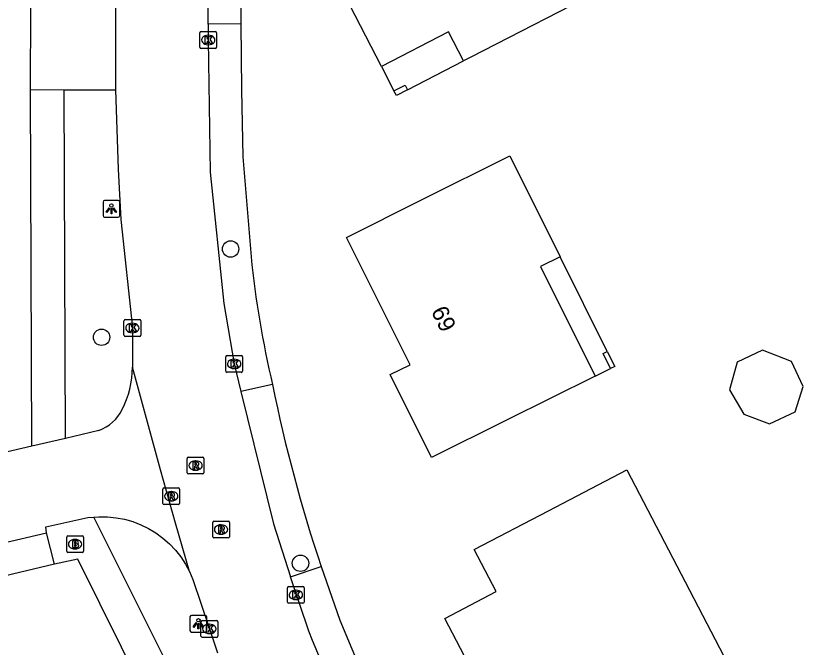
# Model space of a CAD drawing. Extents: x 162722 to 165099, y 384721 to 386283.
# Drawn here: x 163645.06 to 163692.03, y 385039.4 to 385077.05 of the extents above; entities that cross this region are included whole.
import ezdxf

# ---------------------------------------------------------------- set-up
doc = ezdxf.new("R2010")
doc.units = 0
for name, color, linetype in [('IMGEO_Boom', 7, 'Continuous'), ('IMGEO_Brandkraan', 7, 'Continuous'), ('IMGEO_Kolk', 7, 'Continuous'), ('IMGEO_Lichtpunt', 7, 'Continuous'), ('IMGEO_Pand', 7, 'Continuous'), ('IMGEO_Pand_nummerreeks', 7, 'Continuous'), ('IMGEO_Pand_overbouw', 7, 'Continuous'), ('IMGEO_Parkeervlak_open', 7, 'Continuous'), ('IMGEO_Rijbaan_lokaal_open', 7, 'Continuous'), ('IMGEO_Rioolput', 7, 'Continuous'), ('IMGEO_Voetpad_open', 7, 'Continuous')]:
    doc.layers.add(name, color=color, linetype=linetype)

msp = doc.modelspace()

# ---------------------------------------------------------------- linework, layer by layer
at = {"layer": 'IMGEO_Boom'}
for centre in [(163657.877, 385063.146), (163650.18, 385057.883), (163662.044, 385044.403)]:
    msp.add_circle(centre, 0.489, dxfattribs=at)
at = {"layer": 'IMGEO_Brandkraan'}
for p, q in [((163648.099, 385045.118), (163648.099, 385045.97)), ((163648.174, 385046.044), (163649.026, 385046.044)), ((163648.587, 385045.824), (163648.612, 385045.824)), ((163649.1, 385045.97), (163649.1, 385045.118)), ((163649.026, 385045.044), (163648.174, 385045.044)), ((163648.61, 385045.264), (163648.585, 385045.264))]:
    msp.add_line(p, q, dxfattribs=at)
for points in [[(163648.099, 385045.118), (163648.099, 385045.97)], [(163648.174, 385046.044), (163649.026, 385046.044)], [(163649.1, 385045.97), (163649.1, 385045.118)], [(163648.447, 385045.744), (163648.447, 385045.344), (163648.66, 385045.344)], [(163648.678, 385045.744), (163648.447, 385045.744)], [(163648.626, 385045.663), (163648.572, 385045.663), (163648.572, 385045.587)], [(163648.572, 385045.587), (163648.625, 385045.587)], [(163648.634, 385045.511), (163648.572, 385045.511), (163648.572, 385045.43)], [(163648.572, 385045.43), (163648.634, 385045.43)], [(163649.026, 385045.044), (163648.174, 385045.044)]]:
    msp.add_lwpolyline(points, dxfattribs=at)
for centre, radius, start, end in [((163648.176, 385045.968), 0.0765, 91.552, 178.448), ((163648.176, 385045.968), 0.0765, 91.552, 178.448), ((163649.024, 385045.968), 0.0765, 1.552, 88.448), ((163649.024, 385045.968), 0.0765, 1.552, 88.448), ((163648.627, 385045.625), 0.0379, 267.8285, 90.9355), ((163648.635, 385045.47), 0.0404, 269.8759, 90.5077), ((163648.666, 385045.595), 0.251, 268.6676, 293.5347), ((163648.682, 385045.599), 0.145, 59.4692, 91.5367), ((163648.707, 385045.646), 0.0922, 285.5137, 58.1501), ((163648.712, 385045.454), 0.105, 301.3115, 78.989), ((163648.176, 385045.12), 0.0765, 181.552, 268.448), ((163648.176, 385045.12), 0.0765, 181.552, 268.448), ((163649.024, 385045.12), 0.0765, 271.552, 358.448), ((163649.024, 385045.12), 0.0765, 271.552, 358.448)]:
    msp.add_arc(centre, radius, start, end, dxfattribs=at)
for centre, major_axis, ratio, start_param, end_param in [((163648.586, 385045.544), (-0.387, 0.002), 0.722429, 4.712389, 7.853982), ((163648.611, 385045.544), (-0.39, 0.002), 0.717154, 1.570796, 4.712389)]:
    msp.add_ellipse(centre, major_axis=major_axis, ratio=ratio, start_param=start_param, end_param=end_param, dxfattribs=at)
at = {"layer": 'IMGEO_Kolk'}
for p, q in [((163656.043, 385075.183), (163656.043, 385076.035)), ((163656.118, 385076.109), (163656.97, 385076.109)), ((163656.531, 385075.889), (163656.556, 385075.889)), ((163657.044, 385076.035), (163657.044, 385075.183)), ((163656.97, 385075.109), (163656.118, 385075.109)), ((163656.554, 385075.329), (163656.529, 385075.329)), ((163651.518, 385058.008), (163651.518, 385058.86)), ((163651.593, 385058.934), (163652.445, 385058.934)), ((163652.006, 385058.714), (163652.031, 385058.714)), ((163652.519, 385058.86), (163652.519, 385058.008)), ((163652.029, 385058.154), (163652.004, 385058.154)), ((163652.445, 385057.934), (163651.593, 385057.934)), ((163657.588, 385055.865), (163657.588, 385056.717)), ((163657.663, 385056.791), (163658.515, 385056.791)), ((163658.589, 385056.717), (163658.589, 385055.865)), ((163658.076, 385056.571), (163658.101, 385056.571)), ((163658.515, 385055.791), (163657.663, 385055.791)), ((163658.099, 385056.011), (163658.074, 385056.011)), ((163661.341, 385043.018), (163662.193, 385043.018)), ((163661.266, 385042.092), (163661.266, 385042.944)), ((163661.754, 385042.798), (163661.779, 385042.798)), ((163662.267, 385042.944), (163662.267, 385042.092)), ((163661.777, 385042.238), (163661.752, 385042.238)), ((163662.193, 385042.018), (163661.341, 385042.018)), ((163656.108, 385040.062), (163656.108, 385040.914)), ((163656.183, 385040.988), (163657.035, 385040.988)), ((163656.596, 385040.768), (163656.621, 385040.768)), ((163657.109, 385040.914), (163657.109, 385040.062)), ((163656.619, 385040.208), (163656.594, 385040.208)), ((163657.035, 385039.988), (163656.183, 385039.988))]:
    msp.add_line(p, q, dxfattribs=at)
for points in [[(163656.043, 385075.183), (163656.043, 385076.035)], [(163656.118, 385076.109), (163656.97, 385076.109)], [(163657.044, 385076.035), (163657.044, 385075.183)], [(163656.364, 385075.809), (163656.487, 385075.809), (163656.487, 385075.658), (163656.617, 385075.809), (163656.781, 385075.809), (163656.635, 385075.658), (163656.788, 385075.409), (163656.636, 385075.409), (163656.551, 385075.573), (163656.487, 385075.506), (163656.487, 385075.409), (163656.364, 385075.409), (163656.364, 385075.809)], [(163656.97, 385075.109), (163656.118, 385075.109)], [(163651.518, 385058.008), (163651.518, 385058.86)], [(163651.593, 385058.934), (163652.445, 385058.934)], [(163651.839, 385058.634), (163651.962, 385058.634), (163651.962, 385058.483), (163652.092, 385058.634), (163652.256, 385058.634), (163652.11, 385058.483), (163652.263, 385058.234), (163652.111, 385058.234), (163652.026, 385058.398), (163651.962, 385058.331), (163651.962, 385058.234), (163651.839, 385058.234), (163651.839, 385058.634)], [(163652.519, 385058.86), (163652.519, 385058.008)], [(163652.445, 385057.934), (163651.593, 385057.934)], [(163657.588, 385055.865), (163657.588, 385056.717)], [(163657.663, 385056.791), (163658.515, 385056.791)], [(163658.589, 385056.717), (163658.589, 385055.865)], [(163657.909, 385056.491), (163658.032, 385056.491), (163658.032, 385056.34), (163658.162, 385056.491), (163658.326, 385056.491), (163658.18, 385056.34), (163658.333, 385056.091), (163658.181, 385056.091), (163658.096, 385056.255), (163658.032, 385056.188), (163658.032, 385056.091), (163657.909, 385056.091), (163657.909, 385056.491)], [(163658.515, 385055.791), (163657.663, 385055.791)], [(163661.341, 385043.018), (163662.193, 385043.018)], [(163661.266, 385042.092), (163661.266, 385042.944)], [(163661.587, 385042.718), (163661.71, 385042.718), (163661.71, 385042.567), (163661.84, 385042.718), (163662.004, 385042.718), (163661.858, 385042.567), (163662.011, 385042.318), (163661.859, 385042.318), (163661.774, 385042.482), (163661.71, 385042.415), (163661.71, 385042.318), (163661.587, 385042.318), (163661.587, 385042.718)], [(163662.267, 385042.944), (163662.267, 385042.092)], [(163662.193, 385042.018), (163661.341, 385042.018)], [(163656.108, 385040.062), (163656.108, 385040.914)], [(163656.183, 385040.988), (163657.035, 385040.988)], [(163656.429, 385040.688), (163656.552, 385040.688), (163656.552, 385040.537), (163656.682, 385040.688), (163656.846, 385040.688), (163656.7, 385040.537), (163656.853, 385040.288), (163656.701, 385040.288), (163656.616, 385040.452), (163656.552, 385040.385), (163656.552, 385040.288), (163656.429, 385040.288), (163656.429, 385040.688)], [(163657.109, 385040.914), (163657.109, 385040.062)], [(163657.035, 385039.988), (163656.183, 385039.988)]]:
    msp.add_lwpolyline(points, dxfattribs=at)
for centre, start, end in [((163656.12, 385076.033), 91.552, 178.448), ((163656.12, 385076.033), 91.552, 178.448), ((163656.968, 385076.033), 1.552, 88.448), ((163656.968, 385076.033), 1.552, 88.448), ((163656.12, 385075.185), 181.552, 268.448), ((163656.12, 385075.185), 181.552, 268.448), ((163656.968, 385075.185), 271.552, 358.448), ((163656.968, 385075.185), 271.552, 358.448), ((163651.595, 385058.858), 91.552, 178.448), ((163651.595, 385058.858), 91.552, 178.448), ((163652.443, 385058.858), 1.552, 88.448), ((163652.443, 385058.858), 1.552, 88.448), ((163651.595, 385058.01), 181.552, 268.448), ((163651.595, 385058.01), 181.552, 268.448), ((163652.443, 385058.01), 271.552, 358.448), ((163652.443, 385058.01), 271.552, 358.448), ((163657.665, 385056.715), 91.552, 178.448), ((163657.665, 385056.715), 91.552, 178.448), ((163658.513, 385056.715), 1.552, 88.448), ((163658.513, 385056.715), 1.552, 88.448), ((163657.665, 385055.867), 181.552, 268.448), ((163657.665, 385055.867), 181.552, 268.448), ((163658.513, 385055.867), 271.552, 358.448), ((163658.513, 385055.867), 271.552, 358.448), ((163661.343, 385042.942), 91.552, 178.448), ((163661.343, 385042.942), 91.552, 178.448), ((163662.191, 385042.942), 1.552, 88.448), ((163662.191, 385042.942), 1.552, 88.448), ((163661.343, 385042.094), 181.552, 268.448), ((163661.343, 385042.094), 181.552, 268.448), ((163662.191, 385042.094), 271.552, 358.448), ((163662.191, 385042.094), 271.552, 358.448), ((163656.185, 385040.912), 91.552, 178.448), ((163656.185, 385040.912), 91.552, 178.448), ((163657.033, 385040.912), 1.552, 88.448), ((163657.033, 385040.912), 1.552, 88.448), ((163656.185, 385040.064), 181.552, 268.448), ((163656.185, 385040.064), 181.552, 268.448), ((163657.033, 385040.064), 271.552, 358.448), ((163657.033, 385040.064), 271.552, 358.448)]:
    msp.add_arc(centre, 0.0765, start, end, dxfattribs=at)
for centre, major_axis, ratio, start_param, end_param in [((163656.53, 385075.609), (-0.387, 0.002), 0.722429, 4.712389, 7.853982), ((163656.555, 385075.609), (-0.39, 0.002), 0.717154, 1.570796, 4.712389), ((163652.005, 385058.434), (-0.387, 0.002), 0.722429, 4.712389, 7.853982), ((163652.03, 385058.434), (-0.39, 0.002), 0.717154, 1.570796, 4.712389), ((163658.075, 385056.291), (-0.387, 0.002), 0.722429, 4.712389, 7.853982), ((163658.1, 385056.291), (-0.39, 0.002), 0.717154, 1.570796, 4.712389), ((163661.753, 385042.518), (-0.387, 0.002), 0.722429, 4.712389, 7.853982), ((163661.778, 385042.518), (-0.39, 0.002), 0.717154, 1.570796, 4.712389), ((163656.595, 385040.488), (-0.387, 0.002), 0.722429, 4.712389, 7.853982), ((163656.62, 385040.488), (-0.39, 0.002), 0.717154, 1.570796, 4.712389)]:
    msp.add_ellipse(centre, major_axis=major_axis, ratio=ratio, start_param=start_param, end_param=end_param, dxfattribs=at)
at = {"layer": 'IMGEO_Lichtpunt'}
for p, q in [((163651.169, 385066.037), (163650.361, 385066.037)), ((163651.169, 385066.037), (163650.361, 385066.037)), ((163650.267, 385065.942), (163650.267, 385065.135)), ((163650.267, 385065.942), (163650.267, 385065.135)), ((163651.263, 385065.135), (163651.263, 385065.942)), ((163651.263, 385065.135), (163651.263, 385065.942)), ((163650.361, 385065.041), (163651.169, 385065.041)), ((163650.361, 385065.041), (163651.169, 385065.041)), ((163655.453, 385041.204), (163655.453, 385040.397)), ((163655.453, 385041.204), (163655.453, 385040.397)), ((163656.355, 385041.299), (163655.547, 385041.299)), ((163656.355, 385041.299), (163655.547, 385041.299)), ((163656.449, 385040.397), (163656.449, 385041.204)), ((163656.449, 385040.397), (163656.449, 385041.204)), ((163655.547, 385040.303), (163656.355, 385040.303)), ((163655.547, 385040.303), (163656.355, 385040.303))]:
    msp.add_line(p, q, dxfattribs=at)
for points in [[(163650.641, 385065.606), (163650.68, 385065.578), (163650.492, 385065.316), (163650.454, 385065.343), (163650.641, 385065.606)], [(163650.743, 385065.558), (163650.79, 385065.558), (163650.79, 385065.236), (163650.743, 385065.236), (163650.743, 385065.558)], [(163650.853, 385065.578), (163650.891, 385065.605), (163651.078, 385065.343), (163651.039, 385065.315), (163650.853, 385065.578)], [(163655.827, 385040.868), (163655.866, 385040.84), (163655.678, 385040.578), (163655.64, 385040.605), (163655.827, 385040.868)], [(163655.929, 385040.82), (163655.976, 385040.82), (163655.976, 385040.498), (163655.929, 385040.498), (163655.929, 385040.82)], [(163656.039, 385040.84), (163656.077, 385040.867), (163656.264, 385040.605), (163656.225, 385040.577), (163656.039, 385040.84)]]:
    msp.add_lwpolyline(points, dxfattribs=at)
for centre in [(163650.766, 385065.74), (163655.952, 385041.002)]:
    msp.add_circle(centre, 0.0994, dxfattribs=at)
for centre, start, end in [((163650.361, 385065.942), 90, 180), ((163650.361, 385065.942), 90, 180), ((163651.169, 385065.942), 0, 90), ((163651.169, 385065.942), 0, 90), ((163650.361, 385065.135), 180, 270), ((163650.361, 385065.135), 180, 270), ((163651.169, 385065.135), 270, 0), ((163651.169, 385065.135), 270, 360), ((163655.547, 385041.204), 90, 180), ((163655.547, 385041.204), 90, 180), ((163656.355, 385041.204), 0, 90), ((163656.355, 385041.204), 0, 90), ((163655.547, 385040.397), 180, 270), ((163655.547, 385040.397), 180, 270), ((163656.355, 385040.397), 270, 0), ((163656.355, 385040.397), 270, 360)]:
    msp.add_arc(centre, 0.0946, start, end, dxfattribs=at)
at = {"layer": 'IMGEO_Pand'}
for points in [[(163679.813, 385087.074), (163676.927, 385085.586), (163680.415, 385078.819), (163672.209, 385074.588), (163671.765, 385074.358), (163670.871, 385076.092), (163666.871, 385074.029), (163664.681, 385078.277), (163667.911, 385079.942), (163664.662, 385086.243), (163669.107, 385088.535), (163674.138, 385091.129), (163674.809, 385089.828), (163677.64, 385091.288), (163679.813, 385087.074)], [(163668.432, 385072.64), (163667.765, 385072.296), (163667.618, 385072.58), (163668.285, 385072.924), (163668.432, 385072.64)], [(163679.619, 385055.564), (163674.34, 385052.934), (163669.864, 385050.703), (163667.395, 385055.658), (163668.579, 385056.248), (163664.795, 385063.841), (163669.27, 385066.071), (163674.53, 385068.693), (163677.528, 385062.678), (163676.364, 385062.098), (163679.619, 385055.564)], [(163690.022, 385052.719), (163691.538, 385053.436), (163692.029, 385054.95), (163691.337, 385056.446), (163689.596, 385057.107), (163688.088, 385056.394), (163687.639, 385054.755), (163688.487, 385053.301), (163690.022, 385052.719)], [(163680.337, 385057.039), (163680.783, 385056.144), (163680.541, 385056.024), (163680.095, 385056.919), (163680.337, 385057.039)], [(163676.839, 385047.54), (163681.5, 385049.974), (163685.242, 385042.809), (163687.557, 385038.377), (163679.74, 385034.294), (163680.798, 385032.269), (163676.455, 385030), (163670.647, 385041.119), (163673.715, 385042.722), (163672.407, 385045.225), (163676.839, 385047.54)]]:
    msp.add_lwpolyline(points, dxfattribs=at)
at = {"layer": 'IMGEO_Pand_overbouw'}
for points in [[(163671.765, 385074.358), (163670.871, 385076.092), (163666.871, 385074.029), (163667.618, 385072.58), (163668.285, 385072.924), (163668.432, 385072.64)], [(163677.528, 385062.678), (163676.364, 385062.098), (163679.619, 385055.564), (163680.541, 385056.024), (163680.095, 385056.919), (163680.337, 385057.039)]]:
    msp.add_lwpolyline(points, close=True, dxfattribs=at)
at = {"layer": 'IMGEO_Parkeervlak_open'}
for points in [[(163658.479, 385076.581), (163658.518, 385072.645), (163658.603, 385068.634), (163659.1, 385062.687)], [(163660.381, 385055.056), (163658.479, 385054.65)]]:
    msp.add_lwpolyline(points, dxfattribs=at)
for centre, radius, start, end in [((163716.76, 385068.443), 57.947, 185.701, 193.35755), ((163748.35, 385072.73), 89.727, 191.36009, 198.5284)]:
    msp.add_arc(centre, radius, start, end, dxfattribs=at)
at = {"layer": 'IMGEO_Rijbaan_lokaal_open'}
for points in [[(163656.528, 385076.553), (163656.56, 385083.298)], [(163651.014, 385077.529), (163651.012, 385072.642)], [(163656.528, 385076.553), (163656.544, 385075.609), (163656.657, 385067.728), (163657.474, 385059.889), (163658.089, 385056.291), (163658.479, 385054.65)], [(163651.012, 385072.642), (163651.168, 385067.905), (163651.328, 385064.904), (163652.019, 385058.434), (163652.021, 385056.093)], [(163655.425, 385043.908), (163654.586, 385046.801), (163653.687, 385049.972), (163652.021, 385056.093)], [(163658.479, 385054.65), (163660.435, 385046.766), (163661.44, 385043.589)], [(163650.011, 385052.331), (163648.02, 385051.846)], [(163648.02, 385051.846), (163646.024, 385051.391)], [(163646.024, 385051.391), (163618.931, 385045.076)], [(163646.903, 385046.223), (163646.848, 385046.574), (163649.355, 385047.125), (163649.722, 385047.157)], [(163649.722, 385047.157), (163650.016, 385047.176), (163650.53, 385047.172), (163651.042, 385047.123), (163651.548, 385047.028), (163652.043, 385046.888), (163652.524, 385046.705), (163652.986, 385046.479), (163653.426, 385046.213), (163653.841, 385045.909), (163654.227, 385045.568), (163654.581, 385045.195), (163654.901, 385044.792), (163655.183, 385044.361), (163655.425, 385043.908)], [(163618.779, 385039.712), (163621.774, 385040.271), (163634.345, 385043.264), (163644.168, 385045.585), (163646.903, 385046.223)], [(163655.425, 385043.908), (163655.626, 385043.434), (163656.609, 385040.488), (163657.094, 385039.073)], [(163663.652, 385037.67), (163662.755, 385039.803), (163662.534, 385040.358), (163661.44, 385043.589)]]:
    msp.add_lwpolyline(points, dxfattribs=at)
for centre, radius, start, end in [((163646.439, 385056.103), 5.582, 333.008, 359.894), ((163649.176, 385054.689), 2.501, 289.5064, 333.43)]:
    msp.add_arc(centre, radius, start, end, dxfattribs=at)
at = {"layer": 'IMGEO_Rioolput'}
for p, q in [((163655.285, 385049.806), (163655.285, 385050.658)), ((163655.36, 385050.732), (163656.212, 385050.732)), ((163655.773, 385050.512), (163655.798, 385050.512)), ((163656.286, 385050.658), (163656.286, 385049.806)), ((163656.212, 385049.732), (163655.36, 385049.732)), ((163655.796, 385049.952), (163655.771, 385049.952)), ((163653.836, 385047.975), (163653.836, 385048.827)), ((163653.911, 385048.901), (163654.763, 385048.901)), ((163654.324, 385048.681), (163654.349, 385048.681)), ((163654.837, 385048.827), (163654.837, 385047.975)), ((163654.763, 385047.901), (163653.911, 385047.901)), ((163654.347, 385048.121), (163654.322, 385048.121)), ((163656.81, 385045.991), (163656.81, 385046.843)), ((163656.885, 385046.917), (163657.737, 385046.917)), ((163657.811, 385046.843), (163657.811, 385045.991)), ((163657.298, 385046.697), (163657.323, 385046.697)), ((163657.737, 385045.917), (163656.885, 385045.917)), ((163657.321, 385046.137), (163657.296, 385046.137))]:
    msp.add_line(p, q, dxfattribs=at)
for points in [[(163655.285, 385049.806), (163655.285, 385050.658)], [(163655.36, 385050.732), (163656.212, 385050.732)], [(163656.286, 385050.658), (163656.286, 385049.806)], [(163655.874, 385050.43), (163655.622, 385050.432), (163655.622, 385050.032)], [(163655.622, 385050.032), (163655.746, 385050.032), (163655.746, 385050.194), (163655.757, 385050.194)], [(163655.8, 385050.351), (163655.746, 385050.351), (163655.746, 385050.27)], [(163655.746, 385050.27), (163655.798, 385050.27)], [(163655.804, 385050.165), (163655.875, 385050.032), (163656.015, 385050.032), (163655.95, 385050.158)], [(163656.212, 385049.732), (163655.36, 385049.732)], [(163653.836, 385047.975), (163653.836, 385048.827)], [(163653.911, 385048.901), (163654.763, 385048.901)], [(163654.837, 385048.827), (163654.837, 385047.975)], [(163654.425, 385048.599), (163654.173, 385048.601), (163654.173, 385048.201)], [(163654.173, 385048.201), (163654.297, 385048.201), (163654.297, 385048.363), (163654.308, 385048.363)], [(163654.351, 385048.52), (163654.297, 385048.52), (163654.297, 385048.439)], [(163654.297, 385048.439), (163654.349, 385048.439)], [(163654.355, 385048.334), (163654.426, 385048.201), (163654.566, 385048.201), (163654.501, 385048.327)], [(163654.763, 385047.901), (163653.911, 385047.901)], [(163656.81, 385045.991), (163656.81, 385046.843)], [(163656.885, 385046.917), (163657.737, 385046.917)], [(163657.811, 385046.843), (163657.811, 385045.991)], [(163657.399, 385046.615), (163657.147, 385046.617), (163657.147, 385046.217)], [(163657.147, 385046.217), (163657.271, 385046.217), (163657.271, 385046.379), (163657.282, 385046.379)], [(163657.325, 385046.536), (163657.271, 385046.536), (163657.271, 385046.455)], [(163657.271, 385046.455), (163657.323, 385046.455)], [(163657.329, 385046.35), (163657.4, 385046.217), (163657.54, 385046.217), (163657.475, 385046.343)], [(163657.737, 385045.917), (163656.885, 385045.917)]]:
    msp.add_lwpolyline(points, dxfattribs=at)
for centre, radius, start, end in [((163655.362, 385050.656), 0.0765, 91.552, 178.448), ((163655.362, 385050.656), 0.0765, 91.552, 178.448), ((163656.21, 385050.656), 0.0765, 1.552, 88.448), ((163656.21, 385050.656), 0.0765, 1.552, 88.448), ((163655.756, 385050.141), 0.0533, 26.0293, 88.6989), ((163655.782, 385050.459), 0.19, 274.7715, 282.9687), ((163655.806, 385050.255), 0.0964, 77.0061, 93.1865), ((163655.82, 385050.312), 0.0378, 276.6634, 79.6772), ((163655.873, 385050.32), 0.109, 350.3612, 89.416), ((163655.871, 385050.32), 0.112, 277.5842, 350.9817), ((163655.855, 385050.105), 0.108, 29.5134, 73.7905), ((163655.362, 385049.808), 0.0765, 181.552, 268.448), ((163655.362, 385049.808), 0.0765, 181.552, 268.448), ((163656.21, 385049.808), 0.0765, 271.552, 358.448), ((163656.21, 385049.808), 0.0765, 271.552, 358.448), ((163653.913, 385048.825), 0.0765, 91.552, 178.448), ((163653.913, 385048.825), 0.0765, 91.552, 178.448), ((163654.761, 385048.825), 0.0765, 1.552, 88.448), ((163654.761, 385048.825), 0.0765, 1.552, 88.448), ((163654.307, 385048.31), 0.0533, 26.0293, 88.6989), ((163654.333, 385048.628), 0.19, 274.7715, 282.9687), ((163654.357, 385048.424), 0.0964, 77.0061, 93.1865), ((163654.371, 385048.481), 0.0378, 276.6634, 79.6772), ((163654.424, 385048.489), 0.109, 350.3612, 89.416), ((163654.422, 385048.489), 0.112, 277.5842, 350.9817), ((163654.406, 385048.274), 0.108, 29.5134, 73.7905), ((163653.913, 385047.977), 0.0765, 181.552, 268.448), ((163653.913, 385047.977), 0.0765, 181.552, 268.448), ((163654.761, 385047.977), 0.0765, 271.552, 358.448), ((163654.761, 385047.977), 0.0765, 271.552, 358.448), ((163656.887, 385046.841), 0.0765, 91.552, 178.448), ((163656.887, 385046.841), 0.0765, 91.552, 178.448), ((163657.735, 385046.841), 0.0765, 1.552, 88.448), ((163657.735, 385046.841), 0.0765, 1.552, 88.448), ((163657.281, 385046.326), 0.0533, 26.0293, 88.6989), ((163657.307, 385046.644), 0.19, 274.7715, 282.9687), ((163657.331, 385046.44), 0.0964, 77.0061, 93.1865), ((163657.345, 385046.497), 0.0378, 276.6634, 79.6772), ((163657.398, 385046.505), 0.109, 350.3612, 89.416), ((163657.396, 385046.505), 0.112, 277.5842, 350.9817), ((163657.38, 385046.29), 0.108, 29.5134, 73.7905), ((163656.887, 385045.993), 0.0765, 181.552, 268.448), ((163656.887, 385045.993), 0.0765, 181.552, 268.448), ((163657.735, 385045.993), 0.0765, 271.552, 358.448), ((163657.735, 385045.993), 0.0765, 271.552, 358.448)]:
    msp.add_arc(centre, radius, start, end, dxfattribs=at)
for centre, major_axis, ratio, start_param, end_param in [((163655.772, 385050.232), (-0.387, 0.002), 0.722429, 4.712389, 7.853982), ((163655.797, 385050.232), (-0.39, 0.002), 0.717154, 1.570796, 4.712389), ((163654.323, 385048.401), (-0.387, 0.002), 0.722429, 4.712389, 7.853982), ((163654.348, 385048.401), (-0.39, 0.002), 0.717154, 1.570796, 4.712389), ((163657.297, 385046.417), (-0.387, 0.002), 0.722429, 4.712389, 7.853982), ((163657.322, 385046.417), (-0.39, 0.002), 0.717154, 1.570796, 4.712389)]:
    msp.add_ellipse(centre, major_axis=major_axis, ratio=ratio, start_param=start_param, end_param=end_param, dxfattribs=at)
at = {"layer": 'IMGEO_Voetpad_open'}
for points in [[(163658.491, 385083.327), (163658.479, 385076.581)], [(163645.95, 385072.658), (163645.955, 385077.538)], [(163658.479, 385076.581), (163656.528, 385076.553)], [(163646.024, 385051.391), (163645.95, 385072.658)], [(163645.95, 385072.658), (163647.94, 385072.645)], [(163647.94, 385072.645), (163651.012, 385072.642)], [(163648.02, 385051.846), (163647.94, 385072.645)], [(163654.402, 385037.762), (163649.722, 385047.157)], [(163647.366, 385044.347), (163646.903, 385046.223)], [(163652.689, 385036.751), (163648.759, 385044.647), (163647.366, 385044.347)], [(163647.366, 385044.347), (163622.325, 385038.391), (163615.798, 385036.873), (163616.481, 385027.101), (163613.177, 385025.497), (163609.496, 385039.41), (163608.796, 385040.85)], [(163661.44, 385043.589), (163663.274, 385044.217)], [(163663.274, 385044.217), (163664.399, 385041.02), (163665.473, 385038.453)]]:
    msp.add_lwpolyline(points, dxfattribs=at)

# ---------------------------------------------------------------- texts
at = {"layer": 'IMGEO_Pand_nummerreeks'}
msp.add_text('69', height=1, rotation=296.4876, dxfattribs=at).set_placement((163669.808, 385059.432))

doc.saveas('drawing.dxf')
